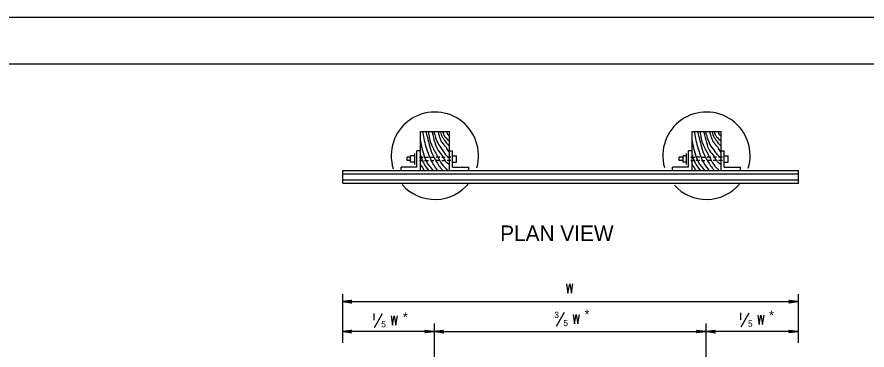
# Model space of a CAD drawing. Extents: x -2340 to 628, y -879 to 309.
# Drawn here: x -738 to -465, y -391.4 to -284.6 of the extents above; entities that cross this region are included whole.
import ezdxf

# ---------------------------------------------------------------- set-up
doc = ezdxf.new("R2010")
doc.units = 0
for name, color, linetype in [('Level 1', 7, 'Continuous'), ('Level 2', 7, 'Continuous'), ('Level 3', 7, 'Continuous'), ('PLT-BNDY', 7, 'Continuous')]:
    doc.layers.add(name, color=color, linetype=linetype)

msp = doc.modelspace()

# ---------------------------------------------------------------- linework, layer by layer
at = {"layer": 'Level 1'}
msp.add_line((-1077.39, -299.56), (-291.39, -299.56), dxfattribs=at)
at = {"layer": 'Level 2'}
for p, q in [((-608.5, -321.24), (-599.13, -321.24)), ((-521.25, -321.24), (-511.88, -321.24)), ((-608.5, -327.49), (-609.63, -327.49)), ((-599.13, -327.49), (-598.13, -327.49)), ((-521.25, -327.49), (-522.38, -327.49)), ((-511.88, -327.49), (-510.88, -327.49)), ((-609.63, -332.74), (-614.63, -332.74)), ((-598.13, -332.74), (-592.88, -332.74)), ((-522.38, -332.74), (-527.5, -332.74)), ((-510.88, -332.74), (-505.63, -332.74)), ((-633.38, -333.74), (-487, -333.74)), ((-633.38, -334.86), (-487, -334.86)), ((-633.38, -336.74), (-487, -336.74)), ((-633.38, -337.86), (-487, -337.86))]:
    msp.add_line(p, q, dxfattribs=at)
at = {"layer": 'Level 3'}
for p, q in [((-608.5, -333.74), (-608.5, -321.24)), ((-599.13, -333.74), (-599.13, -321.24)), ((-521.25, -333.74), (-521.25, -321.24)), ((-511.88, -333.74), (-511.88, -321.24)), ((-609.63, -332.74), (-609.63, -327.49)), ((-598.13, -332.74), (-598.13, -327.49)), ((-522.38, -332.74), (-522.38, -327.49)), ((-510.88, -332.74), (-510.88, -327.49)), ((-612.75, -330.61), (-612.75, -329.49)), ((-611.63, -329.49), (-612.75, -329.49)), ((-611.63, -331.11), (-611.63, -329.11)), ((-610.25, -329.11), (-611.63, -329.11)), ((-610.25, -331.86), (-610.25, -328.36)), ((-608.75, -329.49), (-607.63, -329.49)), ((-607.13, -329.49), (-605.88, -329.49)), ((-605.25, -329.49), (-604.13, -329.49)), ((-602.25, -329.49), (-603.38, -329.49)), ((-601.63, -329.49), (-600.5, -329.49)), ((-598.75, -329.49), (-599.88, -329.49)), ((-598.13, -329.11), (-596.88, -329.11)), ((-596.88, -331.11), (-596.88, -329.11)), ((-525.38, -330.61), (-525.38, -329.49)), ((-524.13, -329.49), (-525.38, -329.49)), ((-524.13, -331.11), (-524.13, -329.11)), ((-523, -329.11), (-524.13, -329.11)), ((-523, -331.86), (-523, -328.36)), ((-521.63, -329.49), (-520.38, -329.49)), ((-518.75, -329.49), (-520, -329.49)), ((-518.25, -329.49), (-517.13, -329.49)), ((-515.25, -329.49), (-516.38, -329.49)), ((-513.38, -329.49), (-514.5, -329.49)), ((-511.5, -329.49), (-512.75, -329.49)), ((-510.88, -329.11), (-509.63, -329.11)), ((-509.63, -331.11), (-509.63, -329.11)), ((-614.63, -333.74), (-614.63, -332.74)), ((-611.63, -330.61), (-612.75, -330.61)), ((-610.25, -331.11), (-611.63, -331.11)), ((-608.75, -330.61), (-607.63, -330.61)), ((-607.13, -330.61), (-605.88, -330.61)), ((-605.25, -330.61), (-604.13, -330.61)), ((-602.25, -330.61), (-603.38, -330.61)), ((-601.63, -330.61), (-600.5, -330.61)), ((-598.75, -330.61), (-599.88, -330.61)), ((-598.13, -331.11), (-596.88, -331.11)), ((-592.88, -333.74), (-592.88, -332.74)), ((-527.5, -333.74), (-527.5, -332.74)), ((-524.13, -330.61), (-525.38, -330.61)), ((-523, -331.11), (-524.13, -331.11)), ((-521.63, -330.61), (-520.38, -330.61)), ((-518.75, -330.61), (-520, -330.61)), ((-518.25, -330.61), (-517.13, -330.61)), ((-515.25, -330.61), (-516.38, -330.61)), ((-513.38, -330.61), (-514.5, -330.61)), ((-511.5, -330.61), (-512.75, -330.61)), ((-510.88, -331.11), (-509.63, -331.11)), ((-505.63, -333.74), (-505.63, -332.74)), ((-633.38, -337.86), (-633.38, -333.74)), ((-487, -337.86), (-487, -333.74)), ((-633.53, -373.48), (-633.53, -389.11)), ((-487.15, -373.48), (-487.15, -389.11)), ((-633.53, -375.86), (-487.15, -375.86)), ((-604.03, -382.86), (-604.03, -408.11)), ((-516.78, -382.86), (-516.78, -408.11)), ((-604.03, -385.48), (-633.53, -385.48)), ((-604.03, -385.48), (-516.78, -385.48)), ((-487.15, -385.48), (-516.78, -385.48))]:
    msp.add_line(p, q, dxfattribs=at)
for points in [[(-561.52, -370.12), (-561.1, -373.12), (-560.53, -370.12), (-559.99, -373.12), (-559.51, -370.12)], [(-630.78, -376.23), (-630.9, -376.11), (-633.53, -375.86), (-630.78, -376.23), (-630.65, -376.36), (-633.53, -375.86), (-630.9, -375.73), (-630.78, -375.48), (-633.53, -375.86), (-630.65, -375.36), (-630.78, -375.48)], [(-490.03, -375.48), (-489.9, -375.73), (-487.15, -375.86), (-490.03, -375.48), (-490.15, -375.36), (-487.15, -375.86), (-489.9, -375.98), (-490.03, -376.23), (-487.15, -375.86), (-490.15, -376.36), (-490.03, -376.23)], [(-564.75, -383.77), (-562.2, -379.25)], [(-505.57, -381.67), (-505.57, -379.43)], [(-505.46, -383.94), (-502.9, -379.43)], [(-623.34, -381.85), (-623.34, -379.61)], [(-623.22, -384.12), (-620.67, -379.61)], [(-617.88, -380.37), (-617.46, -383.37), (-616.89, -380.37), (-616.35, -383.37), (-615.88, -380.37)], [(-559.41, -380.01), (-558.98, -383.01), (-558.42, -380.01), (-557.87, -383.01), (-557.4, -380.01)], [(-500.12, -380.19), (-499.69, -383.19), (-499.12, -380.19), (-498.58, -383.19), (-498.11, -380.19)], [(-630.78, -385.73), (-630.9, -385.73), (-633.53, -385.48), (-630.78, -385.73), (-630.65, -385.98), (-633.53, -385.48), (-630.9, -385.36), (-630.78, -385.11), (-633.53, -385.48), (-630.65, -384.98), (-630.78, -385.11)], [(-606.9, -385.11), (-606.78, -385.36), (-604.03, -385.48), (-606.9, -385.11), (-607.03, -384.98), (-604.03, -385.48), (-606.78, -385.61), (-606.9, -385.73), (-604.03, -385.48), (-607.03, -385.86), (-606.9, -385.73)], [(-601.15, -385.73), (-601.28, -385.73), (-604.03, -385.48), (-601.15, -385.73), (-601.03, -385.98), (-604.03, -385.48), (-601.28, -385.36), (-601.15, -385.11), (-604.03, -385.48), (-601.03, -384.98), (-601.15, -385.11)], [(-519.65, -385.11), (-519.53, -385.36), (-516.78, -385.48), (-519.65, -385.11), (-519.78, -384.98), (-516.78, -385.48), (-519.53, -385.61), (-519.65, -385.73), (-516.78, -385.48), (-519.78, -385.86), (-519.65, -385.73)], [(-513.9, -385.73), (-514.03, -385.73), (-516.78, -385.48), (-513.9, -385.73), (-513.78, -385.98), (-516.78, -385.48), (-514.03, -385.36), (-513.9, -385.11), (-516.78, -385.48), (-513.78, -384.98), (-513.9, -385.11)], [(-490.03, -385.11), (-489.9, -385.36), (-487.15, -385.48), (-490.03, -385.11), (-490.15, -384.98), (-487.15, -385.48), (-489.9, -385.61), (-490.03, -385.73), (-487.15, -385.48), (-490.15, -385.86), (-490.03, -385.73)]]:
    msp.add_lwpolyline(points, dxfattribs=at)
for centre, start, end in [((-603.83, -329.05), 344.085, 197.2873), ((-516.6, -329.05), 343.3743, 195.5154), ((-603.83, -329.05), 221.3222, 321.6878), ((-516.6, -329.05), 222.6593, 319.137)]:
    msp.add_arc(centre, 14.02, start, end, dxfattribs=at)
for points in [[(-607.75, -321.24), (-607.38, -323.49), (-606.75, -326.11), (-605.75, -328.86), (-604.25, -331.99), (-603.13, -333.74)], [(-606.75, -321.24), (-606.25, -323.11), (-604.38, -329.11), (-603, -331.49), (-602, -332.99), (-601.38, -333.74)], [(-605.88, -321.36), (-605.63, -323.24), (-604.63, -326.24), (-602.88, -329.49), (-601.5, -331.86), (-599.75, -333.74)], [(-604.75, -321.24), (-604.5, -322.36), (-603.63, -325.61), (-602.75, -327.36), (-601.25, -329.36), (-600.38, -330.86), (-599.25, -331.74)], [(-604.13, -321.36), (-603.63, -323.24), (-602.63, -325.49), (-601.13, -327.61), (-600.25, -328.86), (-599.25, -329.74)], [(-602.75, -321.36), (-602.5, -322.61), (-602.13, -323.61), (-601.63, -324.74), (-600.25, -326.36), (-599.5, -327.74), (-599.25, -327.99)], [(-602, -321.36), (-601.5, -322.99), (-600.88, -323.86), (-600.13, -324.99), (-599.25, -325.86)], [(-601.25, -321.36), (-600.88, -322.61), (-600.25, -323.36), (-599.25, -324.24)], [(-600, -321.36), (-599.88, -321.99), (-599.63, -322.24), (-599.25, -322.61)], [(-520.5, -321.24), (-520.13, -323.49), (-519.5, -326.11), (-518.63, -328.86), (-517.13, -331.99), (-515.88, -333.74)], [(-519.5, -321.24), (-519, -323.11), (-517.13, -329.11), (-515.75, -331.49), (-514.75, -332.99), (-514.13, -333.74)], [(-518.63, -321.36), (-518.38, -323.24), (-517.38, -326.24), (-515.63, -329.49), (-514.25, -331.86), (-512.63, -333.74)], [(-517.5, -321.24), (-517.25, -322.36), (-516.38, -325.61), (-515.63, -327.36), (-514.13, -329.36), (-513.13, -330.86), (-512, -331.74)], [(-516.88, -321.36), (-516.38, -323.24), (-515.5, -325.49), (-514, -327.61), (-513, -328.86), (-512, -329.74)], [(-515.63, -321.36), (-515.25, -322.61), (-514.88, -323.61), (-514.38, -324.74), (-513, -326.36), (-512.25, -327.74), (-512, -327.99)], [(-514.75, -321.36), (-514.25, -322.99), (-513.63, -323.86), (-512.88, -324.99), (-512, -325.86)], [(-514.13, -321.36), (-513.63, -322.61), (-513, -323.36), (-512, -324.24)], [(-512.75, -321.36), (-512.63, -321.99), (-512.5, -322.24), (-512, -322.61)], [(-608.5, -324.24), (-607.63, -327.99), (-606.5, -330.99), (-604.5, -333.74)], [(-521.25, -324.24), (-520.38, -327.99), (-519.25, -330.99), (-517.25, -333.74)], [(-608.5, -328.86), (-607.5, -331.36), (-605.88, -333.74)], [(-521.25, -328.86), (-520.25, -331.36), (-518.63, -333.74)], [(-608.5, -331.86), (-607.75, -332.99), (-607.13, -333.86)], [(-521.25, -331.86), (-520.5, -332.99), (-519.88, -333.86)]]:
    msp.add_spline(points, degree=3, dxfattribs=at)
at = {"layer": 'PLT-BNDY'}
msp.add_lwpolyline([(-1117.39, -284.56), (-276.39, -284.56), (-276.39, -878.56), (-1117.39, -878.56)], close=True, dxfattribs=at)

# ---------------------------------------------------------------- texts
at = {"layer": 'Level 2'}
for p in [(-614.11, -382.32), (-555.76, -381.4), (-496.49, -381.77)]:
    msp.add_text('*', height=3, dxfattribs=at).set_placement(p)
at = {"layer": 'Level 3'}
for s, height, p in [('PLAN VIEW', 5, (-582.86, -356.43)), ('3', 2, (-565.48, -381.1)), ('5', 2, (-621.05, -384.08)), ('5', 2, (-562.57, -383.73)), ('5', 2, (-503.28, -383.9))]:
    msp.add_text(s, height=height, dxfattribs=at).set_placement(p)

doc.saveas('drawing.dxf')
